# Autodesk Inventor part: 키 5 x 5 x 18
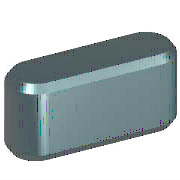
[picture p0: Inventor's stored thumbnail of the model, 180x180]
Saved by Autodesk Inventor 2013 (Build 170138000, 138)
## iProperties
Created: 2012-02
Part Number: 키 5 x 5 x 18
Material: 강철, 연강
Description: 키 및 해당 키홈
Document SubType Name: Modeling
Standard: KS B 1311
Designer: P15F
Standards Organization: KS
Language: ko-KR
Size Designation: 5 x 5 x 18
Categories: <MemberInstance><Categories><Category DisplayName="샤프트 부품" InternalName="7f7aeb1f-a693-4053-b835-cee3144e0d98" Mnemonic="SHFT"><Category DisplayName="키" Interna
Density: 1 g/cm^3
IsCustomPart: 1
Author: P15F
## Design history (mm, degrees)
workplane "Work Plane1"
workplane "Work Plane2"
sketch "스케치1"
  geometry: L1 (2.5, 2.5)-(15.5, 2.5); L2 (15.5, -2.5)-(2.5, -2.5); L3 (0, 9.4)-(0, -7.4) reference; L4 (-5, 0)-(30, 0) reference; L5 (18, 0)-(18, 7); A1 r 2.5 centre (2.5, 0) between (2.5, 2.5) and (2.5, -2.5); A2 r 2.5 centre (15.5, 0) between (15.5, -2.5) and (15.5, 2.5)
  constraints: 6 end point, 5 point on circle, 4 tangent, 3 point on line, 2 centre point, 1 horizontal, 1 parallel, 1 perpendicular
  dimensions: "d0" = 2.5 radius of A1 (= 0.5 x PB); "d13" = 2.5 radius of A2 (= 0.5 x PB); "d14" = 18 distance between parallel lines of L5 L3 (= NLG)
extrude "본체1" new body sketch "스케치1" taper "d3" = 0 deg; stored distance "d4" = 10
workplane "Work Plane3"
body "Solid1"
chamfer "모따기1" distance "d8" = 0.4 (= PHH); stored, may be unused: second distance "d9" = 0.4 (= PHH), angle "d15" = 45 deg
other parameters: "d1" = -3 (= -PNT), "d2" = 2 (= PH - PNT), "NLG" = 18 [user parameter; used in 3 equation terms], "PB" = 5 [user parameter; used in 2 equation terms], "PNT" = 3 [user parameter; used in 2 equation terms], "PH" = 5 [user parameter; used in 1 equation term], "PHH" = 0.4 [user parameter; used in 2 equation terms], "d10" = 0, "d16" = 0, "d17" = 0, "d18" = 0, "WDMIN" = 12 [user parameter], "PLB2" = 18 (= NLG) [user parameter], "WDMAX" = 17 [user parameter], "PLB1" = 18 (= NLG) [user parameter], "RR" = 0.16 [user parameter], "PUEB" = 2.3 [user parameter]
